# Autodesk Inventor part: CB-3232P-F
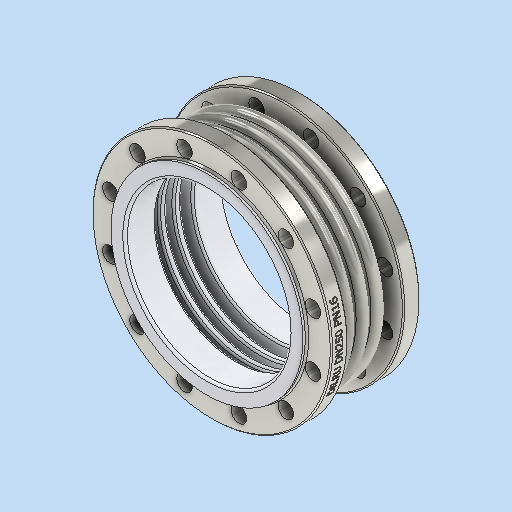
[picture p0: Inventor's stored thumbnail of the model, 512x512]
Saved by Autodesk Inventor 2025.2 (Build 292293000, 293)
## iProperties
Company: DN.RU
Created: 2026-04
Part Number: CB-3232P-F
Material: Типовые
Document SubType Name: Modeling
Designer: DN.RU
Density: 5.82692 g/cm^3
Appearance: По умолчанию
Description: D140-02145
Mass: 29400 g
Surface Area: 11413.4 cm^2
Volume: 5040.48 cm^3
Author: DN.RU
Title: Компенсатор сильфонный осевой DN.ru Ду250 Ру16
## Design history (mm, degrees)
sketch "Эскиз1"
  geometry: L1 (0, 0)-(0, -75); L2 (148.25, -75)-(148.25, 0); L3 (148.25, 0)-(0, 0); L4 (148.25, 0)-(148.25, 0); L5 (118.25, 0)-(178.25, 0); L6 (118.25, -9)-(178.25, -9); L7 (178.25, 9)-(118.25, 9); L8 (178.25, -6)-(118.25, -6); L9 (118.25, 6)-(178.25, 6); L10 (178.25, -16)-(118.25, -16); L11 (118.25, -19)-(178.25, -19); L12 (118.25, -25)-(178.25, -25); L13 (118.25, -34)-(178.25, -34); L14 (178.25, -31)-(118.25, -31); L15 (0, -75)-(148.25, -75); L16 (148.25, -75)-(138.25, -75); L17 (138.25, -75)-(138.25, -31); L18 (148.25, -19)-(145.25, -19); L19 (145.25, -19)-(145.25, -6); L20 (148.25, 6)-(145.25, 6); L21 (145.25, 6)-(145.25, 0); L22 (0, -75)-(0, -47); L23 (0, -47)-(202.5, -47); L24 (202.5, -47)-(202.5, -75); L25 (202.5, -75)-(0, -75); L26 (148.25, -47)-(148.25, -65); L27 (148.25, -65)-(153.25, -65); L28 (153.25, -65)-(153.25, -47); L29 (153.25, -47)-(148.25, -47); L30 (148.25, 0)-(187.25, 0); A1 r 9 centre (118.25, 0) between (118.25, 9) and (118.25, -9); A2 r 9 centre (178.25, 0) between (178.25, -9) and (178.25, 9); A3 r 6 centre (118.25, 0) between (118.25, 6) and (118.25, -6); A4 r 6 centre (178.25, 0) between (178.25, -6) and (178.25, 6); A5 r 6 centre (118.25, -25) between (118.25, -19) and (118.25, -31); A6 r 9 centre (118.25, -25) between (118.25, -16) and (118.25, -34); A7 r 6 centre (178.25, -25) between (178.25, -31) and (178.25, -19); A8 r 9 centre (178.25, -25) between (178.25, -34) and (178.25, -16); 20 further points
  constraints: 64 end point, 17 point on circle, 14 point on line, 8 centre point, 7 parallel, 5 perpendicular, 4 tangent, 3 midpoint, 2 vertical, 1 horizontal, 25 other
  dimensions: "d0" = 75 distance of L1.start L1.end; "d3" = 0 distance of L2.end L4.end; "d4" = 30 distance of L4.end L5.end; "d5" = 18 diameter of A2; "d6" = 3 distance between parallel lines of L6 L8; "d9" = 25 distance of L4.end point (148.25, -25); "d18" = 3 distance of L18.start L18.end; "d19" = 3 distance of L20.start L20.end; "d27" = 138.25 distance between parallel lines of L1 L17; "d28" = 10 distance between parallel lines of L2 L17; "d29" = 28 distance of L1.end L22.end; "d30" = 202.5 distance of L22.end L23.end; "d31" = 18 distance of L26.start L26.end; "d32" = 5 distance of L27.end L26.end
revolve "Вращение1" sketch "Эскиз1" stored, may be unused: angle "d20" = 360 deg
sketch "Эскиз3" dims "d33" = 355
  geometry: L1 (0, 0)-(74.331, 19.917); L2 (0, 0)-(76.954, 0); C1 r 13 at (171.452, 45.94); C2 r 13 at (125.511, 125.511); C3 r 13 at (45.94, 171.452); C4 r 13 at (-45.94, 171.452); C5 r 138.25 at (0, 0) reference; C6 r 160 at (0, 0); C7 r 202.5 at (0, 0) reference; C8 r 13 at (-125.511, 125.511); C9 r 13 at (-171.452, 45.94); C10 r 13 at (-171.452, -45.94); C11 r 13 at (-125.511, -125.511); C12 r 13 at (-45.94, -171.452); C13 r 13 at (45.94, -171.452); C14 r 13 at (125.511, -125.511); C15 r 13 at (171.452, -45.94); 1 further point
  constraints: 13 centre point, 4 end point, 2 coincident, 1 equal length, 1 horizontal, 1 point on line, 28 other
  dimensions: "d34" = 15 deg angle of L2 L1; "d35" = 26 diameter of C1; "d38" = 360 deg dimension on point (0, 0) C1.centre (derived); "d40" = 320 diameter of C6
  node "Эскиз — круговой массив1" dims "d38" = 360 deg (derived)
extrude "Выдавливание1" cut sketch "Эскиз3" stored distance "d41" = 10; taper "d42" = 0 deg
extrude "Выдавливание2" join sketch "Эскиз3" distance "d43" = 4; taper "d44" = 0 deg
chamfer "Фаска2" distance "d45" = 4; stored, may be unused: second distance "d46" = 2, angle "d47" = 45 deg
chamfer "Фаска3" distance "d48" = 2; stored, may be unused: second distance "d49" = 2, angle "d50" = 45 deg
mirror "Зеркальное отражение2"
fillet "Сопряжение2" dims "d51" = 3
node "РабПлоскость2"
sketch "Эскиз4"
  geometry: L1 (-79.877, 6.714)-(96.758, 6.714); L2 (96.758, 6.714)-(96.758, -34.405); L3 (96.758, -34.405)-(-79.877, -34.405); L4 (-79.877, -34.405)-(-79.877, 6.714); 1 further point
  constraints: 2 other
feature "Рельеф2" sketch "Эскиз4" dims "d3" = 0, "d52" = 0.1, "d53" = 0
sketch "Эскиз5"
  geometry: C1 r 138.25 at (0, 0) reference; C2 r 162.25 at (0, 0); 1 further point
  constraints: 1 centre point
  dimensions: "d54" = 24 radial gap between concentric circles of C1 C2
extrude "Выдавливание3" join sketch "Эскиз5" distance "d55" = 4; taper "d56" = 0 deg
fillet "Сопряжение3" dims "d57" = 4
mirror "Зеркальное отражение3"
feature "Ɋ耀Ɍ耀Ɏ耀ɐ耀ɒ耀ɔ耀ɖ耀ɘ耀" dims "d0" = 75, "d3" = 0, "d4" = 30, "d5" = 18, "d6" = 3, "d7" = 20, "d9" = 25, "d10" = 10, "d12" = 10, "d18" = 3, "d19" = 3, "d20" = 360 deg, "d27" = 138.25, "d28" = 10, "d29" = 28, "d30" = 202.5, "d31" = 18, "d32" = 5, "d33" = 355, "d34" = 15 deg, "d35" = 26, "d36" = 120, "d38" = 360 deg (derived), "d40" = 320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
node "Твердое тело1"
node "Эскиз — прямоугольный массив1" dims "d9" = 25, "d12" = 10
